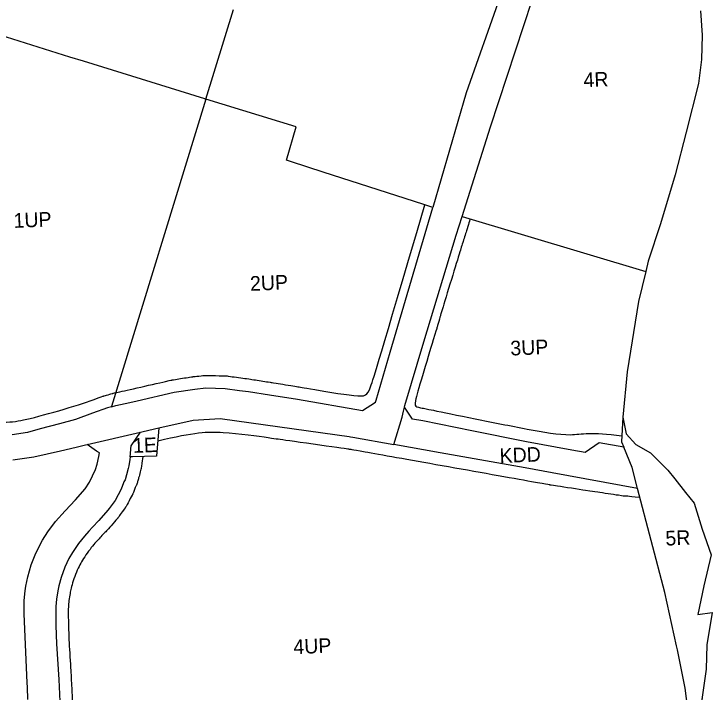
# Model space of a CAD drawing. Extents: x 7417062 to 7419348, y 5549957 to 5551711.
# Drawn here: x 7418637.3 to 7418971.7, y 5550486.1 to 5550810.6 of the extents above; entities that cross this region are included whole.
import ezdxf

# ---------------------------------------------------------------- set-up
doc = ezdxf.new("R2010")
doc.units = 0
for name, color, linetype in [('GRANICA_PLANU_po_wejsciu_MYDLNIKI', 7, 'Continuous'), ('linie_rozgraniczające_po_wejsciu_MYDLNIKI', 7, 'Continuous'), ('Linie_zabudowy_po_wejsciu_MYDLNIKI', 7, 'Continuous'), ('oznaczenia_przeznaczen_po_wejsciu_MYDLNIKI', 7, 'Continuous')]:
    doc.layers.add(name, color=color, linetype=linetype)

msp = doc.modelspace()

# ---------------------------------------------------------------- linework, layer by layer
at = {"layer": 'GRANICA_PLANU_po_wejsciu_MYDLNIKI'}
msp.add_lwpolyline([(7418966.12, 5550812.07), (7418966.93, 5550800.53), (7418966.67, 5550788.84), (7418965.19, 5550777.32), (7418959.19, 5550754.08), (7418953.98, 5550733.63), (7418946.98, 5550710.17), (7418941.11, 5550692.36), (7418939.89, 5550687.35), (7418936.39, 5550673.01), (7418931.06, 5550639.24), (7418928.87, 5550617.55), (7418930.57, 5550609.69), (7418935.18, 5550604.48), (7418942.17, 5550600.54), (7418950.5, 5550592.28), (7418953.86, 5550588.04), (7418958.96, 5550581.55), (7418963.15, 5550576.43), (7418966.99, 5550563.96), (7418971.17, 5550551.7), (7418967.75, 5550536.95), (7418964.86, 5550523.11), (7418971.66, 5550524.05), (7418969.23, 5550508.6), (7418968.84, 5550497.04), (7418964.99, 5550470.04)], dxfattribs=at)
at = {"layer": 'linie_rozgraniczające_po_wejsciu_MYDLNIKI'}
for p, q in [((7418879.3, 5550845.1), (7418853.95, 5550772.84)), ((7418865.61, 5550756.51), (7418885.44, 5550817.28)), ((7418729.15, 5550769.84), (7418742.52, 5550812.78)), ((7418966.12, 5550812.07), (7418966.93, 5550800.53)), ((7418664.03, 5550789.96), (7418630.53, 5550800.4)), ((7418966.93, 5550800.53), (7418966.67, 5550788.84)), ((7418670.57, 5550788.05), (7418664.03, 5550789.96)), ((7418684.45, 5550783.78), (7418670.57, 5550788.05)), ((7418966.67, 5550788.84), (7418965.19, 5550777.32)), ((7418716.89, 5550773.69), (7418684.45, 5550783.78)), ((7418965.19, 5550777.32), (7418959.19, 5550754.08)), ((7418728.78, 5550769.95), (7418716.89, 5550773.69)), ((7418853.95, 5550772.84), (7418837.86, 5550718.02)), ((7418729.14, 5550769.78), (7418684.08, 5550622.74)), ((7418728.87, 5550769.86), (7418728.78, 5550769.95)), ((7418728.78, 5550769.95), (7418729.15, 5550769.84)), ((7418729.14, 5550769.78), (7418728.87, 5550769.86)), ((7418772.53, 5550756.65), (7418729.14, 5550769.78)), ((7418767.79, 5550740.64), (7418772.53, 5550756.65)), ((7418852.04, 5550713.71), (7418865.61, 5550756.51)), ((7418959.19, 5550754.08), (7418953.98, 5550733.63)), ((7418770.25, 5550739.85), (7418767.79, 5550740.64)), ((7418785.44, 5550734.95), (7418770.25, 5550739.85)), ((7418833.69, 5550719.37), (7418785.44, 5550734.95)), ((7418953.98, 5550733.63), (7418946.98, 5550710.17)), ((7418837.86, 5550718.02), (7418833.69, 5550719.37)), ((7418817.54, 5550648.78), (7418837.86, 5550718.02)), ((7418849.17, 5550704.66), (7418852.04, 5550713.71)), ((7418852.04, 5550713.71), (7418939.89, 5550687.35)), ((7418946.98, 5550710.17), (7418941.11, 5550692.36)), ((7418946.98, 5550710.17), (7418946.98, 5550710.17)), ((7418833.65, 5550653.69), (7418849.17, 5550704.66)), ((7418941.11, 5550692.36), (7418939.89, 5550687.35)), ((7418939.89, 5550687.35), (7418936.39, 5550673.01)), ((7418936.39, 5550673.01), (7418931.06, 5550639.24)), ((7418936.39, 5550673.01), (7418936.39, 5550673.01)), ((7418824.56, 5550623.15), (7418833.65, 5550653.69)), ((7418810.76, 5550625.8), (7418817.54, 5550648.78)), ((7418931.06, 5550639.24), (7418928.87, 5550617.55)), ((7418931.06, 5550639.24), (7418931.06, 5550639.24)), ((7418696.33, 5550625.47), (7418714.06, 5550629.52)), ((7418714.06, 5550629.52), (7418723.88, 5550631.07)), ((7418723.88, 5550631.07), (7418729.12, 5550631.6)), ((7418729.12, 5550631.6), (7418738.44, 5550631.4)), ((7418738.44, 5550631.4), (7418745.32, 5550630.45)), ((7418745.32, 5550630.45), (7418749.67, 5550629.86)), ((7418749.67, 5550629.86), (7418759.75, 5550628.29)), ((7418759.75, 5550628.29), (7418773.16, 5550626.16)), ((7418773.16, 5550626.16), (7418804.17, 5550620.85)), ((7418810.48, 5550624.85), (7418810.76, 5550625.8)), ((7418684.06, 5550622.61), (7418682.11, 5550622.04)), ((7418684.06, 5550622.61), (7418686.05, 5550623.18)), ((7418684.08, 5550622.74), (7418684.06, 5550622.61)), ((7418686.05, 5550623.18), (7418692.76, 5550624.68)), ((7418692.76, 5550624.68), (7418696.33, 5550625.47)), ((7418804.17, 5550620.85), (7418810.48, 5550624.85)), ((7418824.36, 5550622.33), (7418824.56, 5550623.15)), ((7418674.94, 5550619.48), (7418666.75, 5550616.56)), ((7418682.11, 5550622.04), (7418674.94, 5550619.48)), ((7418823.16, 5550617.6), (7418823.88, 5550620.45)), ((7418823.88, 5550620.45), (7418824.36, 5550622.33)), ((7418828.12, 5550616.74), (7418824.36, 5550622.33)), ((7418666.75, 5550616.56), (7418659.08, 5550614.48)), ((7418706.64, 5550612.45), (7418723.12, 5550616.25)), ((7418723.12, 5550616.25), (7418736.06, 5550617.04)), ((7418736.06, 5550617.04), (7418764.56, 5550612.97)), ((7418819.3, 5550604.54), (7418823.16, 5550617.6)), ((7418833.19, 5550615.81), (7418828.12, 5550616.74)), ((7418856.55, 5550611.05), (7418833.19, 5550615.81)), ((7418928.87, 5550617.55), (7418928.35, 5550605.81)), ((7418928.87, 5550617.55), (7418930.57, 5550609.69)), ((7418659.08, 5550614.48), (7418649.82, 5550611.96)), ((7418699.22, 5550610.73), (7418706.64, 5550612.45)), ((7418706.64, 5550612.45), (7418705.63, 5550599)), ((7418764.56, 5550612.97), (7418797.81, 5550608.33)), ((7418643.73, 5550610.31), (7418636.38, 5550609.15)), ((7418649.82, 5550611.96), (7418643.73, 5550610.31)), ((7418672.34, 5550604.52), (7418697.84, 5550610.41)), ((7418693.38, 5550603.88), (7418697.84, 5550610.41)), ((7418697.84, 5550610.41), (7418699.22, 5550610.73)), ((7418882.76, 5550605.81), (7418856.55, 5550611.05)), ((7418930.57, 5550609.69), (7418935.18, 5550604.48)), ((7418797.81, 5550608.33), (7418798.49, 5550608.23)), ((7418798.49, 5550608.23), (7418799.54, 5550608.02)), ((7418799.54, 5550608.02), (7418819.3, 5550604.54)), ((7418904.51, 5550601.89), (7418882.76, 5550605.81)), ((7418928.35, 5550605.81), (7418929.39, 5550603.23)), ((7418659.51, 5550601.56), (7418667.08, 5550603.31)), ((7418667.08, 5550603.31), (7418671.5, 5550604.33)), ((7418671.5, 5550604.33), (7418672.34, 5550604.52)), ((7418676.85, 5550601.39), (7418672.34, 5550604.52)), ((7418693.18, 5550600), (7418693.3, 5550602.46)), ((7418693.3, 5550602.46), (7418693.38, 5550603.88)), ((7418841.47, 5550600.62), (7418819.3, 5550604.54)), ((7418917.57, 5550605.32), (7418910.95, 5550600.69)), ((7418929.39, 5550603.23), (7418917.57, 5550605.32)), ((7418933.35, 5550593.45), (7418929.39, 5550603.23)), ((7418929.39, 5550603.23), (7418929.39, 5550603.23)), ((7418935.18, 5550604.48), (7418935.18, 5550604.48)), ((7418935.18, 5550604.48), (7418942.17, 5550600.54)), ((7418646.84, 5550598.7), (7418659.51, 5550601.56)), ((7418678.34, 5550600.57), (7418676.85, 5550601.39)), ((7418677.9, 5550598.74), (7418678.34, 5550600.57)), ((7418692.98, 5550598.62), (7418693.18, 5550600)), ((7418705.63, 5550599), (7418694.08, 5550598.66)), ((7418882.1, 5550593.37), (7418841.47, 5550600.62)), ((7418910.95, 5550600.69), (7418904.51, 5550601.89)), ((7418942.17, 5550600.54), (7418942.17, 5550600.54)), ((7418942.17, 5550600.54), (7418950.5, 5550592.28)), ((7418636.7, 5550597.27), (7418646.84, 5550598.7)), ((7418677.15, 5550595.2), (7418677.9, 5550598.74)), ((7418692.8, 5550597.43), (7418692.33, 5550594.25)), ((7418692.98, 5550598.62), (7418692.8, 5550597.43)), ((7418694.08, 5550598.66), (7418692.98, 5550598.62)), ((7418673.48, 5550586.47), (7418676.33, 5550592.59)), ((7418676.33, 5550592.59), (7418677.15, 5550595.2)), ((7418692, 5550593), (7418691.21, 5550590.07)), ((7418692.33, 5550594.25), (7418692, 5550593)), ((7418895.13, 5550591.04), (7418882.1, 5550593.37)), ((7418936, 5550583.4), (7418933.35, 5550593.45)), ((7418933.35, 5550593.45), (7418933.35, 5550593.45)), ((7418933.35, 5550593.45), (7418933.35, 5550593.45)), ((7418950.5, 5550592.28), (7418950.5, 5550592.28)), ((7418950.5, 5550592.28), (7418950.5, 5550592.28)), ((7418950.5, 5550592.28), (7418953.86, 5550588.04)), ((7418691.21, 5550590.07), (7418690.52, 5550587.66)), ((7418936, 5550583.4), (7418895.13, 5550591.04)), ((7418671.39, 5550583.32), (7418673.48, 5550586.47)), ((7418689.74, 5550586.15), (7418688.69, 5550583.22)), ((7418689.97, 5550586.59), (7418689.74, 5550586.15)), ((7418690.52, 5550587.66), (7418689.97, 5550586.59)), ((7418953.86, 5550588.04), (7418953.86, 5550588.04)), ((7418953.86, 5550588.04), (7418958.96, 5550581.55)), ((7418666.79, 5550578.09), (7418671.39, 5550583.32)), ((7418688.69, 5550583.22), (7418685.73, 5550577.77)), ((7418958.96, 5550581.55), (7418963.15, 5550576.43)), ((7418661.78, 5550572.82), (7418666.79, 5550578.09)), ((7418685.73, 5550577.77), (7418682.91, 5550573.89)), ((7418963.15, 5550576.43), (7418966.99, 5550563.96)), ((7418657.11, 5550567.71), (7418661.78, 5550572.82)), ((7418682.33, 5550573.03), (7418677.98, 5550568.09)), ((7418682.91, 5550573.89), (7418682.33, 5550573.03)), ((7418653.44, 5550562.73), (7418657.11, 5550567.71)), ((7418677.98, 5550568.09), (7418674.98, 5550564.93)), ((7418650.89, 5550558.7), (7418653.44, 5550562.73)), ((7418673.2, 5550563.06), (7418671.05, 5550560.67)), ((7418674.98, 5550564.93), (7418673.2, 5550563.06)), ((7418966.99, 5550563.96), (7418971.17, 5550551.7)), ((7418671.05, 5550560.67), (7418668.27, 5550557.17)), ((7418647.76, 5550552.57), (7418650.89, 5550558.7)), ((7418668.27, 5550557.17), (7418665.34, 5550552.91)), ((7418645.54, 5550546.9), (7418647.76, 5550552.57)), ((7418665.34, 5550552.91), (7418663.59, 5550549.89)), ((7418663.59, 5550549.89), (7418661.66, 5550545.88)), ((7418971.17, 5550551.7), (7418967.75, 5550536.95)), ((7418643.9, 5550541.21), (7418645.54, 5550546.9)), ((7418661.66, 5550545.88), (7418659.84, 5550540.95)), ((7418642.93, 5550536.65), (7418643.9, 5550541.21)), ((7418659.84, 5550540.95), (7418658.76, 5550536.95)), ((7418642.69, 5550534.55), (7418642.93, 5550536.65)), ((7418658.76, 5550536.95), (7418658.26, 5550534.57)), ((7418967.75, 5550536.95), (7418964.86, 5550523.11)), ((7418967.75, 5550536.95), (7418967.75, 5550536.95)), ((7418642.2, 5550529.9), (7418642.69, 5550534.55)), ((7418658.26, 5550534.57), (7418657.62, 5550530.48)), ((7418642.17, 5550523.41), (7418642.2, 5550529.9)), ((7418657.62, 5550530.48), (7418657.29, 5550527.07)), ((7418657.29, 5550527.07), (7418657.28, 5550523.18)), ((7418643.68, 5550490.39), (7418642.17, 5550523.41)), ((7418657.28, 5550523.18), (7418657.4, 5550517.85)), ((7418964.86, 5550523.11), (7418971.66, 5550524.05)), ((7418971.66, 5550524.05), (7418969.23, 5550508.6)), ((7418971.66, 5550524.05), (7418971.66, 5550524.05)), ((7418657.4, 5550517.85), (7418657.67, 5550509.18)), ((7418657.67, 5550509.18), (7418658.76, 5550492.02)), ((7418955.11, 5550506.21), (7418954.68, 5550508.17)), ((7418954.68, 5550508.17), (7418954.68, 5550508.17)), ((7418954.68, 5550508.17), (7418954.68, 5550508.17)), ((7418954.68, 5550508.17), (7418954.68, 5550508.17)), ((7418958.85, 5550487.92), (7418955.11, 5550506.21)), ((7418969.23, 5550508.6), (7418968.84, 5550497.04)), ((7418968.84, 5550497.04), (7418964.99, 5550470.04)), ((7418968.84, 5550497.04), (7418968.84, 5550497.04)), ((7418658.76, 5550492.02), (7418659.71, 5550471.56)), ((7418643.71, 5550488.33), (7418643.68, 5550490.39)), ((7418643.98, 5550482.48), (7418643.71, 5550488.33)), ((7418961.03, 5550470.75), (7418958.85, 5550487.92))]:
    msp.add_line(p, q, dxfattribs=at)
msp.add_lwpolyline([(7418954.68, 5550508.17), (7418949.11, 5550533.62), (7418936, 5550583.4)], dxfattribs=at)
at = {"layer": 'Linie_zabudowy_po_wejsciu_MYDLNIKI'}
for points in [[(7418575.61, 5550624.91), (7418595.4, 5550620.94), (7418600.76, 5550615.16), (7418616.6, 5550614.76), (7418635.85, 5550615.14), (7418642.47, 5550616.19), (7418664.95, 5550622.29), (7418680.09, 5550627.69), (7418680.32, 5550627.77), (7418680.44, 5550627.8), (7418684.38, 5550628.95), (7418684.64, 5550629.02), (7418684.75, 5550629.04), (7418695, 5550631.32), (7418712.72, 5550635.37), (7418713.03, 5550635.44), (7418713.12, 5550635.45), (7418722.95, 5550637), (7418723.25, 5550637.04), (7418723.28, 5550637.04), (7418728.52, 5550637.57), (7418728.87, 5550637.59), (7418729.25, 5550637.6), (7418738.57, 5550637.4), (7418738.59, 5550637.4), (7418738.99, 5550637.37), (7418739.26, 5550637.34), (7418750.49, 5550635.8), (7418750.59, 5550635.79), (7418760.67, 5550634.22), (7418760.68, 5550634.22), (7418760.69, 5550634.22), (7418774.1, 5550632.08), (7418774.17, 5550632.07), (7418804.83, 5550626.83), (7418807.35, 5550628.39), (7418812.18, 5550644.74), (7418834.07, 5550719.25)], [(7418855.72, 5550712.24), (7418855.34, 5550711.02), (7418854.68, 5550708.88), (7418854.66, 5550708.82), (7418854.4, 5550708.01), (7418851.86, 5550699.84), (7418851.86, 5550699.83), (7418847.72, 5550686.56), (7418841.84, 5550667.19), (7418841.82, 5550667.12), (7418841.56, 5550666.29), (7418839.92, 5550660.61), (7418839.91, 5550660.57), (7418839.89, 5550660.51), (7418839.1, 5550657.95), (7418832.41, 5550635.61), (7418828.91, 5550623.74), (7418829.64, 5550622.56), (7418834.27, 5550621.71), (7418834.39, 5550621.69), (7418857.75, 5550616.93), (7418883.88, 5550611.71), (7418905.25, 5550607.85), (7418913.62, 5550610.84), (7418928.51, 5550608.68)], [(7418936.91, 5550579.18), (7418930.62, 5550579.81), (7418930.3, 5550579.79), (7418929.9, 5550579.78), (7418929.51, 5550579.81), (7418929.17, 5550579.85), (7418914.5, 5550582.02), (7418914.48, 5550582.02), (7418894.23, 5550585.11), (7418894.2, 5550585.12), (7418894.08, 5550585.14), (7418840.41, 5550594.72), (7418798.5, 5550602.11), (7418798.37, 5550602.14), (7418797.48, 5550602.32), (7418763.73, 5550607.03), (7418763.71, 5550607.03), (7418735.82, 5550611.02), (7418723.99, 5550610.3), (7418706.17, 5550606.18)], [(7418699.07, 5550598.8), (7418698.27, 5550593.38), (7418698.26, 5550593.32), (7418698.19, 5550592.93), (7418698.13, 5550592.7), (7418697.01, 5550588.52), (7418696.98, 5550588.42), (7418696.29, 5550586.01), (7418696.28, 5550585.97), (7418696.15, 5550585.59), (7418696.01, 5550585.23), (7418695.85, 5550584.9), (7418695.25, 5550583.75), (7418694.34, 5550581.21), (7418694.32, 5550581.15), (7418694.18, 5550580.79), (7418694.01, 5550580.44), (7418693.96, 5550580.36), (7418691, 5550574.9), (7418690.85, 5550574.64), (7418690.63, 5550574.31), (7418690.58, 5550574.25), (7418687.83, 5550570.45), (7418687.31, 5550569.68), (7418687.23, 5550569.57), (7418687, 5550569.26), (7418686.83, 5550569.06), (7418682.48, 5550564.12), (7418682.39, 5550564.02), (7418682.33, 5550563.96), (7418677.6, 5550558.98), (7418675.63, 5550556.79), (7418673.1, 5550553.6), (7418670.41, 5550549.69), (7418668.89, 5550547.08), (7418667.19, 5550543.54), (7418665.56, 5550539.13), (7418664.59, 5550535.55), (7418664.16, 5550533.5), (7418663.58, 5550529.73), (7418663.29, 5550526.77), (7418663.28, 5550523.24), (7418663.39, 5550518.01), (7418663.66, 5550509.46), (7418664.75, 5550492.4), (7418664.75, 5550492.3), (7418665.76, 5550470.65)]]:
    msp.add_open_spline(points, degree=3, dxfattribs=at)

# ---------------------------------------------------------------- texts
at = {"layer": 'oznaczenia_przeznaczen_po_wejsciu_MYDLNIKI'}
for s, p in [('4R', (7418910.21, 5550775.48)), ('1UP', (7418637.22, 5550708.19)), ('2UP', (7418750.49, 5550678.06)), ('3UP', (7418875.18, 5550647.11)), ('1E', (7418694.45, 5550600.51)), ('KDD', (7418870.02, 5550595.65)), ('5R', (7418949.45, 5550556.13)), ('4UP', (7418771.26, 5550504.18))]:
    msp.add_text(s, height=7, rotation=2.323, dxfattribs=at).set_placement(p)

doc.saveas('drawing.dxf')
